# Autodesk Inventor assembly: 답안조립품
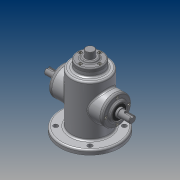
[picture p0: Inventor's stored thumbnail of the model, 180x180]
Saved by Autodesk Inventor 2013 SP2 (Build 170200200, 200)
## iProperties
Created: 2014-12
Part Number: 답안조립품
Document SubType Name: Assembly
Designer: CADB303
Author: CADB303
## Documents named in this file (12)
- C:\Users\CADB303\Desktop\441228V1018\답안조립품.iam
- C:\Users\CADB303\Desktop\441228V1018\본체.ipt
- C:\Users\CADB303\Desktop\441228V1018\M3x0.5x8.ipt
- M3x0.5.ipt
- C:\Users\CADB303\Desktop\441228V1018\베어링 6002.ipt
- 베어링 6002.ipt
- C:\Users\CADB303\Desktop\441228V1018\상단커버.ipt
- C:\Users\CADB303\Desktop\441228V1018\슬라이드.ipt
- C:\Users\CADB303\Desktop\441228V1018\오일실.ipt
- 오일실.ipt
- C:\Users\CADB303\Desktop\441228V1018\커버.ipt
- C:\Users\CADB303\Desktop\441228V1018\편심축.ipt
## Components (12 placed, 1 different names)
1. M3x0.5:3 — 각도:1
2. M3x0.5:4
3. M3x0.5:5
4. M3x0.5:6
5. M3x0.5:1 — 각도:2
6. M3x0.5:7
7. M3x0.5:8
8. M3x0.5:9
9. M3x0.5:2 — 각도:3
10. M3x0.5:10
11. M3x0.5:11
12. M3x0.5:12
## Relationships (3: Angle 3)
- 각도:1 [Angle]: M3x0.5:3
- 각도:2 [Angle]: M3x0.5:1
- 각도:3 [Angle]: M3x0.5:2
